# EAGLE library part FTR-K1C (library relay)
NETZRELAIS FTR-K1CK024W1XUM 16A/250VAC 1 Umschaltkontakt Distributor: Conrad Electronic Bestell Nr.: 504389-13 - 24V Source: http://www2.produktinfo.conrad.com/datenblaetter/500000-524999/504389-da-01-de-NETZRELAIS_FTR-K1CK024W1XUM_16A_250VAC.pdf
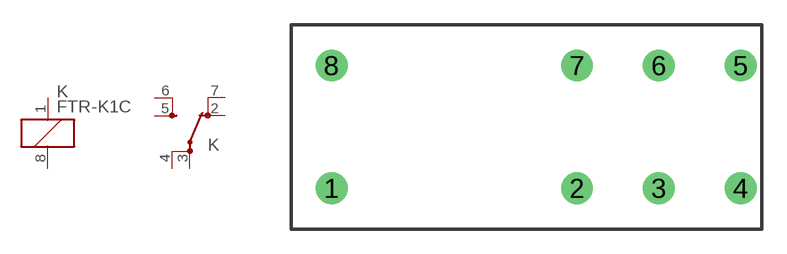
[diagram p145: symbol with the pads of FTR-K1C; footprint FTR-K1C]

Designator prefix K; gates K=K -1=U-X2

## FTR-K1C (OC_FARNELL: unknown; OC_NEWARK: unknown)  [FTR-K1C]
1  K:1  pas
2  -1:OA  pas
3  -1:PA  pas
4  -1:PB  pas
5  -1:SA  pas
6  -1:SB  pas
7  -1:OB  pas
8  K:2  pas

## Footprint FTR-K1C (pad centres in mm)
Miniatur-Leistungsrelais 1 Wechsler Distributor: Conrad Electronic Source: http://www2.produktinfo.conrad.com/datenblaetter/500000-524999/504389-da-01-de-NETZRELAIS_FTR-K1CK024W1XUM_16A_250VAC.pdf
drill 1.3 pad 1.93 round: 1 -12.5,-3.75; 2 2.5,-3.75; 3 7.5,-3.75; 4 12.5,-3.75; 5 12.5,3.75; 6 7.5,3.75; 7 2.5,3.75; 8 -12.5,3.75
